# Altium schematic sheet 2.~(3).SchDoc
size 420 x 297 mm
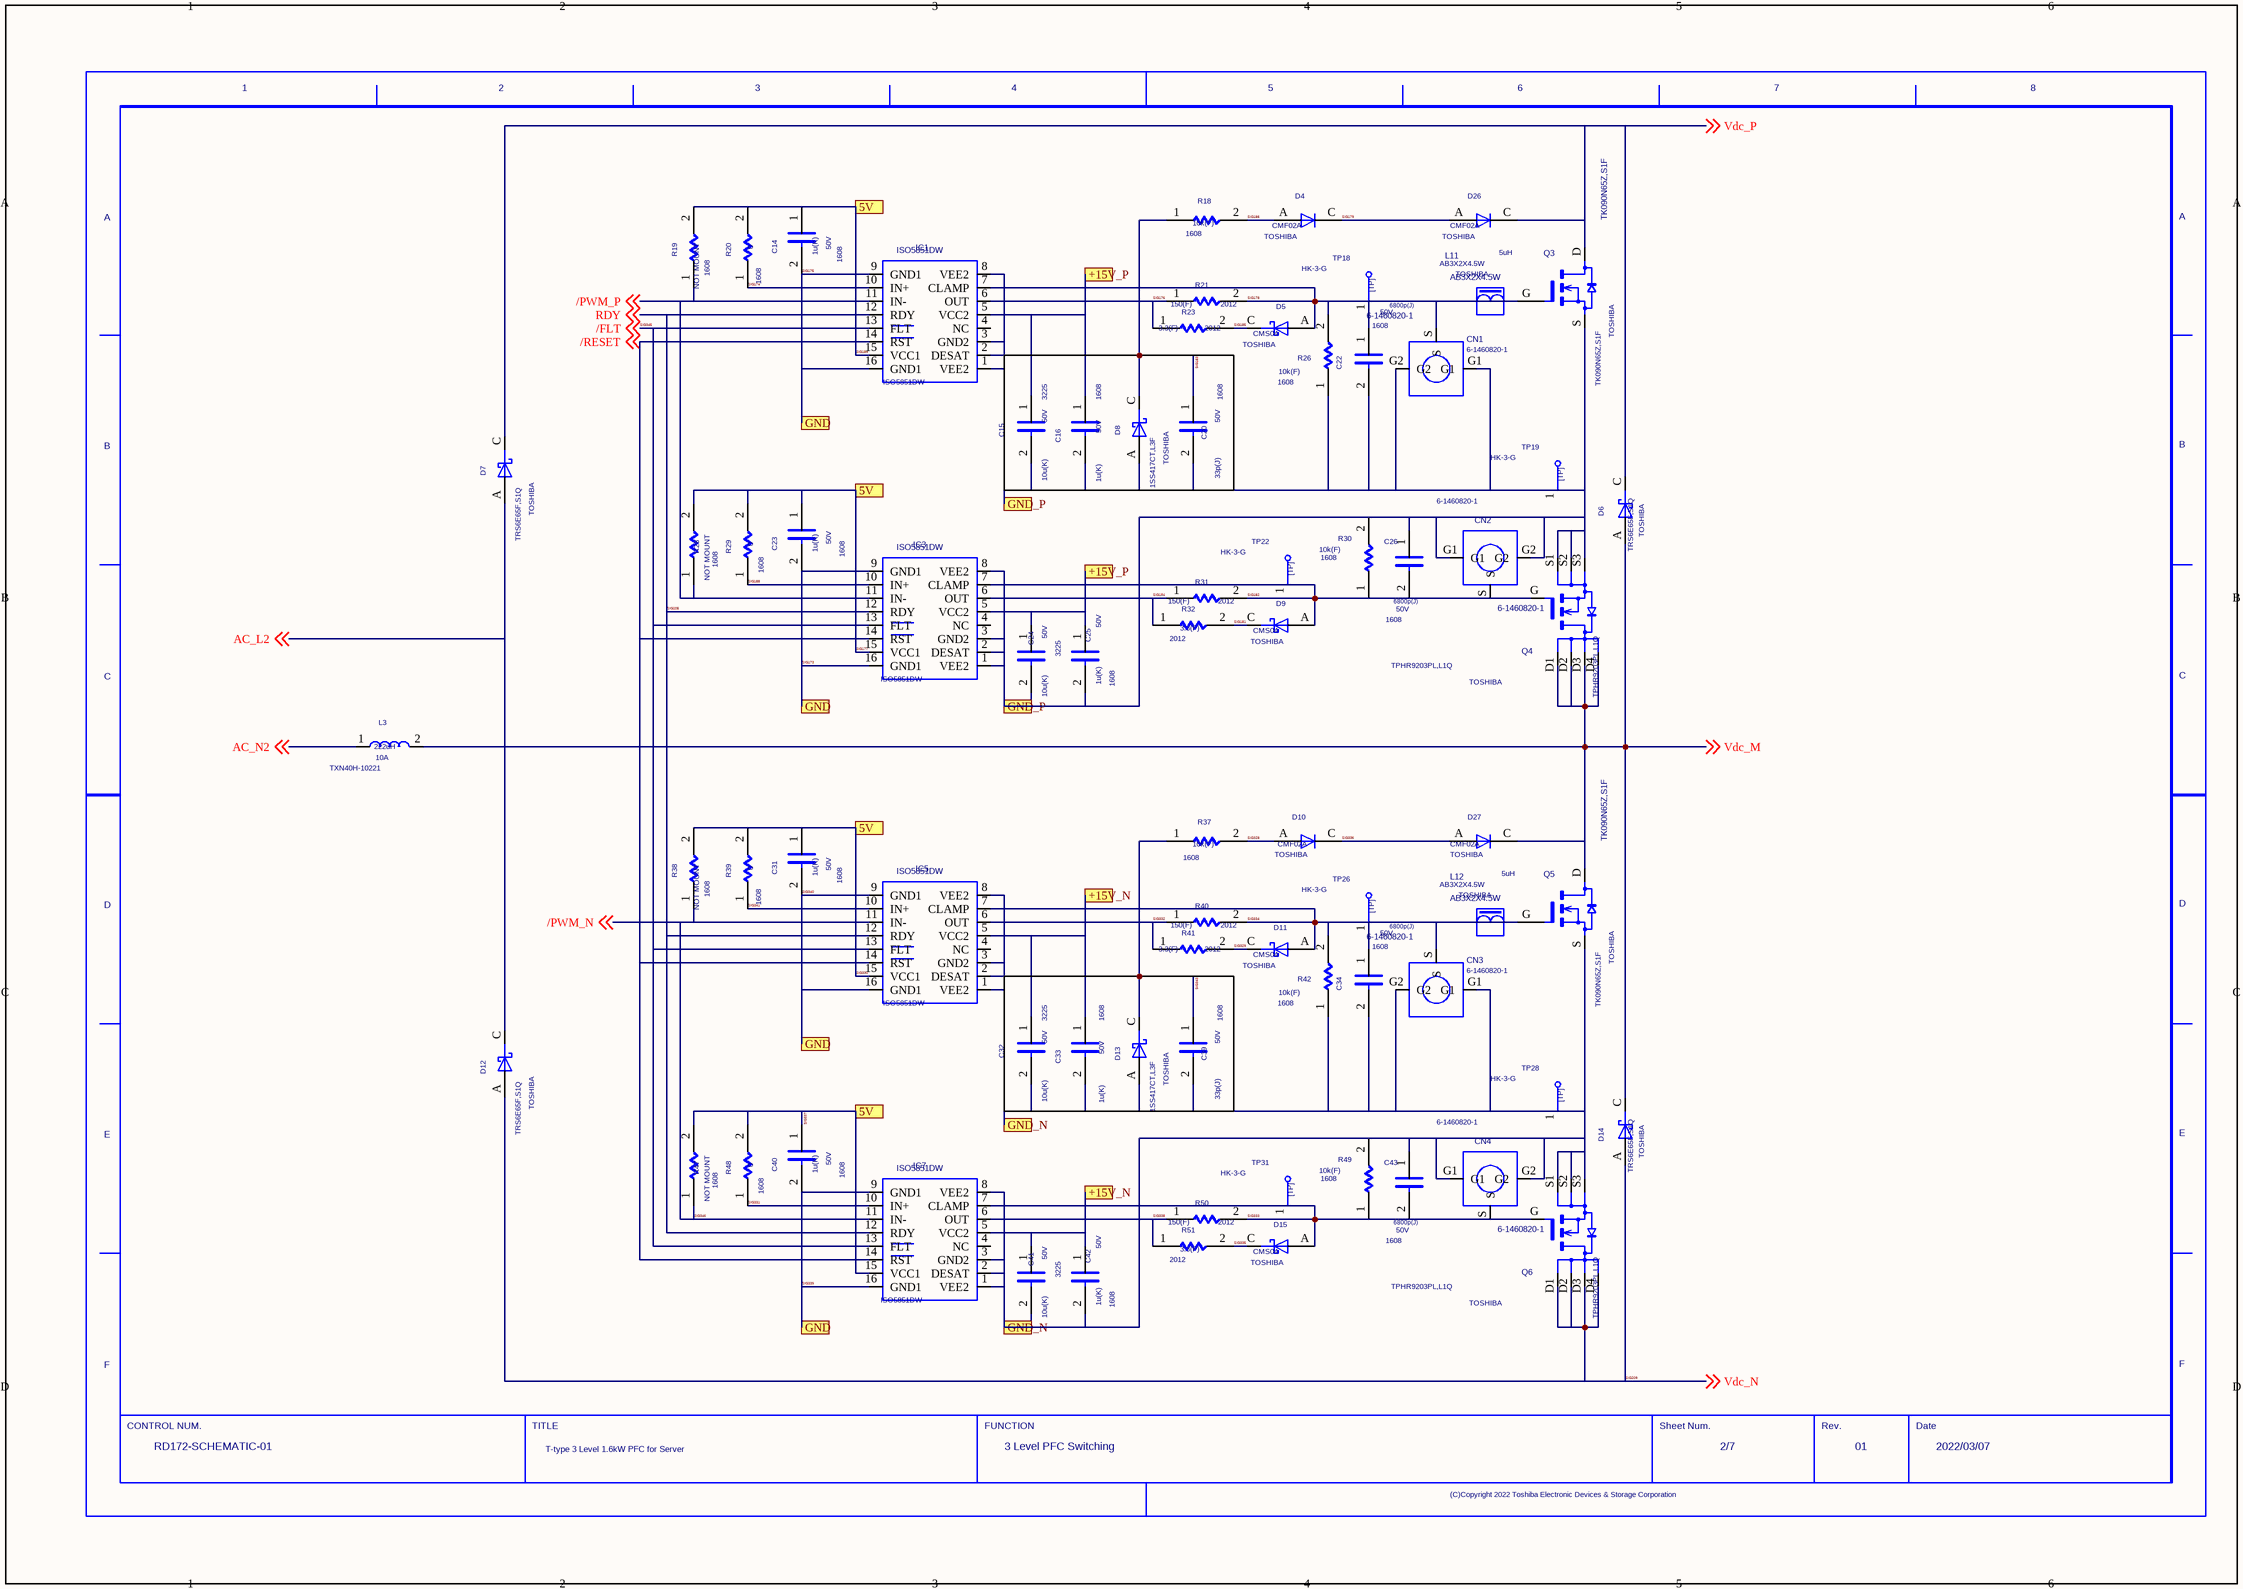
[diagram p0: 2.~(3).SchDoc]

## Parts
C14  SIZECODESMD: 1608  VAL2: 50V  VAL1: 1u(K)  (hidden comment: C)
C15  SIZECODESMD: 3225  VAL2: 50V  VAL1: 10u(K)  (hidden comment: C)
C16  SIZECODESMD: 1608  VAL2: 50V  VAL1: 1u(K)  (hidden comment: C)
C20  SIZECODESMD: 1608  VAL2: 50V  VAL1: 33p(J)  (hidden comment: C)
C22  SIZECODESMD: 1608  VAL2: 50V  VAL1: 6800p(J)  (hidden comment: C)
C23  SIZECODESMD: 1608  VAL2: 50V  VAL1: 1u(K)  (hidden comment: C)
C24  SIZECODESMD: 3225  VAL2: 50V  VAL1: 10u(K)  (hidden comment: C)
C25  SIZECODESMD: 1608  VAL2: 50V  VAL1: 1u(K)  (hidden comment: C)
C26  SIZECODESMD: 1608  VAL2: 50V  VAL1: 6800p(J)  (hidden comment: C)
C31  SIZECODESMD: 1608  VAL2: 50V  VAL1: 1u(K)  (hidden comment: C)
C32  SIZECODESMD: 3225  VAL2: 50V  VAL1: 10u(K)  (hidden comment: C)
C33  SIZECODESMD: 1608  VAL2: 50V  VAL1: 1u(K)  (hidden comment: C)
C34  SIZECODESMD: 1608  VAL2: 50V  VAL1: 6800p(J)  (hidden comment: C)
C39  SIZECODESMD: 1608  VAL2: 50V  VAL1: 33p(J)  (hidden comment: C)
C40  SIZECODESMD: 1608  VAL2: 50V  VAL1: 1u(K)  (hidden comment: C)
C41  SIZECODESMD: 3225  VAL2: 50V  VAL1: 10u(K)  (hidden comment: C)
C42  SIZECODESMD: 1608  VAL2: 50V  VAL1: 1u(K)  (hidden comment: C)
C43  SIZECODESMD: 1608  VAL2: 50V  VAL1: 6800p(J)  (hidden comment: C)
CN1  6-1460820-1
CN2  6-1460820-1
CN3  6-1460820-1
CN4  6-1460820-1
D4  VAL3: CMF02A  USERCOMPTEXT3: TOSHIBA  (hidden comment: D)
D5  USERCOMPTEXT3: TOSHIBA  VAL3: CMS04  (hidden comment: SBD)
D6  VAL3: TRS6E65F,S1Q  USERCOMPTEXT3: TOSHIBA  (hidden comment: SBD)
D7  USERCOMPTEXT3: TOSHIBA  VAL3: TRS6E65F,S1Q  (hidden comment: SBD)
D8  USERCOMPTEXT3: TOSHIBA  VAL3: 1SS417CT,L3F  (hidden comment: SBD)
D9  USERCOMPTEXT3: TOSHIBA  VAL3: CMS04  (hidden comment: SBD)
D10  VAL3: CMF02A  USERCOMPTEXT3: TOSHIBA  (hidden comment: D)
D11  USERCOMPTEXT3: TOSHIBA  VAL3: CMS04  (hidden comment: SBD)
D12  USERCOMPTEXT3: TOSHIBA  VAL3: TRS6E65F,S1Q  (hidden comment: SBD)
D13  USERCOMPTEXT3: TOSHIBA  VAL3: 1SS417CT,L3F  (hidden comment: SBD)
D14  VAL3: TRS6E65F,S1Q  USERCOMPTEXT3: TOSHIBA  (hidden comment: SBD)
D15  USERCOMPTEXT3: TOSHIBA  VAL3: CMS04  (hidden comment: SBD)
D26  VAL3: CMF02A  USERCOMPTEXT3: TOSHIBA  (hidden comment: D)
D27  VAL3: CMF02A  USERCOMPTEXT3: TOSHIBA  (hidden comment: D)
IC1  ISO5851DW
IC3  ISO5851DW
IC5  ISO5851DW
IC7  ISO5851DW
L3  VAL3: TXN40H-10221  VAL2: 10A  VAL1: 222uH  (hidden comment: L)
L11  AB3X2X4.5W  USERCOMPTEXT3: TOSHIBA  VAL1: 5uH
L12  AB3X2X4.5W  USERCOMPTEXT3: TOSHIBA  VAL1: 5uH
Q3  TK090N65Z,S1F  USERCOMPTEXT3: TOSHIBA
Q4  TPHR9203PL,L1Q  USERCOMPTEXT3: TOSHIBA
Q5  TK090N65Z,S1F  USERCOMPTEXT3: TOSHIBA
Q6  TPHR9203PL,L1Q  USERCOMPTEXT3: TOSHIBA
R18  SIZECODESMD: 1608  VAL1: 10k(F)  (hidden comment: R)
R19  SIZECODESMD: 1608  NOTMOUNT: NOT MOUNT  (hidden comment: R)
R20  SIZECODESMD: 1608  VAL1: 0  (hidden comment: R)
R21  SIZECODESMD: 2012  VAL1: 150(F)  (hidden comment: R)
R23  SIZECODESMD: 2012  VAL1: 3.3(F)  (hidden comment: R)
R26  SIZECODESMD: 1608  VAL1: 10k(F)  (hidden comment: R)
R28  SIZECODESMD: 1608  NOTMOUNT: NOT MOUNT  (hidden comment: R)
R29  SIZECODESMD: 1608  VAL1: 0  (hidden comment: R)
R30  SIZECODESMD: 1608  VAL1: 10k(F)  (hidden comment: R)
R31  SIZECODESMD: 2012  VAL1: 150(F)  (hidden comment: R)
R32  SIZECODESMD: 2012  VAL1: 3.3(F)  (hidden comment: R)
R37  SIZECODESMD: 1608  VAL1: 10k(F)  (hidden comment: R)
R38  SIZECODESMD: 1608  NOTMOUNT: NOT MOUNT  (hidden comment: R)
R39  SIZECODESMD: 1608  VAL1: 0  (hidden comment: R)
R40  SIZECODESMD: 2012  VAL1: 150(F)  (hidden comment: R)
R41  SIZECODESMD: 2012  VAL1: 3.3(F)  (hidden comment: R)
R42  SIZECODESMD: 1608  VAL1: 10k(F)  (hidden comment: R)
R47  SIZECODESMD: 1608  NOTMOUNT: NOT MOUNT  (hidden comment: R)
R48  SIZECODESMD: 1608  VAL1: 0  (hidden comment: R)
R49  SIZECODESMD: 1608  VAL1: 10k(F)  (hidden comment: R)
R50  SIZECODESMD: 2012  VAL1: 150(F)  (hidden comment: R)
R51  SIZECODESMD: 2012  VAL1: 3.3(F)  (hidden comment: R)
TP18  VAL3: HK-3-G  (hidden comment: TP)
TP19  VAL3: HK-3-G  (hidden comment: TP)
TP22  VAL3: HK-3-G  (hidden comment: TP)
TP26  VAL3: HK-3-G  (hidden comment: TP)
TP28  VAL3: HK-3-G  (hidden comment: TP)
TP31  VAL3: HK-3-G  (hidden comment: TP)
U?  DATE: 2022/03/07  REVISION: 01  SHEETNUMBER: 2/7  FUNCTION: 3 Level PFC Switching  TITLE: T-type 3 Level 1.6kW PFC for Server  DRAWINGNUMBER: RD172-SCHEMATIC-01  (hidden comment: WAKU_DEF100)

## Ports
5V, +15V_N, +15V_P, GND, GND_N, GND_P

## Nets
+15V_N: C32.1 C33.1 C41.1 C42.1 IC5.5(VCC2) IC7.5(VCC2) ; port +15V_N
+15V_P: C15.1 C16.1 C24.1 C25.1 IC1.5(VCC2) IC3.5(VCC2) ; port +15V_P
/PWM_P: IC1.11(IN-) IC3.11(IN-) R19.1 R28.1 ; off-sheet /PWM_P
/RESET: IC1.14(RST) IC3.14(RST) IC5.14(RST) IC7.14(RST) ; off-sheet /RESET
AC_L2: D7.A D12.C ; off-sheet AC_L2
AC_N2: L3.1 ; off-sheet AC_N2
GND_N: C32.2 C33.2 C34.2 C39.2 C41.2 C42.2 C43.1 CN3.G1 CN3.G2 CN4.G1 CN4.G2 D13.A IC5.1(VEE2) IC5.3(GND2) IC5.8(VEE2) IC7.1(VEE2) IC7.2(DESAT) IC7.3(GND2) IC7.8(VEE2) Q5.S Q6.S1 Q6.S2 Q6.S3 R42.1 R49.2 TP28.1 ; port GND_N
GND_P: C15.2 C16.2 C20.2 C22.2 C24.2 C25.2 C26.1 CN1.G1 CN1.G2 CN2.G1 CN2.G2 D8.A IC1.1(VEE2) IC1.3(GND2) IC1.8(VEE2) IC3.1(VEE2) IC3.2(DESAT) IC3.3(GND2) IC3.8(VEE2) Q3.S Q4.S1 Q4.S2 Q4.S3 R26.1 R30.2 TP19.1 ; port GND_P
SIG173: C14.2 C23.2 C31.2 C40.2 IC1.9(GND1) IC1.16(GND1) IC3.9(GND1) IC3.16(GND1) IC5.9(GND1) IC5.16(GND1) IC7.9(GND1) IC7.16(GND1) ; port GND  [also labelled SIG175, SIG339, SIG340]
SIG174: IC1.10(IN+) R20.1
SIG176: IC1.6(OUT) R21.1 R23.1
SIG177: C14.1 C23.1 C31.1 C40.1 IC1.15(VCC1) IC3.15(VCC1) IC5.15(VCC1) IC7.15(VCC1) R19.2 R20.2 R28.2 R29.2 R38.2 R39.2 R47.2 R48.2 ; port 5V  [also labelled SIG189, SIG330, SIG337]
SIG178: C22.1 CN1.S D5.A IC1.7(CLAMP) Q3.G R21.2 R26.2 TP18.1
SIG179: D4.C D26.A
SIG181: D9.C R32.2
SIG182: C26.2 CN2.S D9.A IC3.7(CLAMP) Q4.G R30.1 R31.2 TP22.1
SIG183: C20.1 D8.C IC1.2(DESAT) R18.1
SIG184: IC3.6(OUT) R31.1 R32.1
SIG185: D5.C R23.2
SIG186: D4.A R18.2
SIG188: IC3.10(IN+) R29.1
SIG205: IC1.12(RDY) IC3.12(RDY) IC5.12(RDY) IC7.12(RDY) ; off-sheet RDY  [also labelled RDY]
SIG209: D12.A D14.A Q6.D1 Q6.D2 Q6.D3 Q6.D4 ; off-sheet Vdc_N  [also labelled Vdc_N]
SIG328: D10.A R37.2
SIG329: D11.C R41.2
SIG331: IC7.10(IN+) R48.1
SIG332: IC5.6(OUT) R40.1 R41.1
SIG333: C43.2 CN4.S D15.A IC7.7(CLAMP) Q6.G R49.1 R50.2 TP31.1
SIG334: C34.1 CN3.S D11.A IC5.7(CLAMP) Q5.G R40.2 R42.2 TP26.1
SIG335: D15.C R51.2
SIG336: D10.C D27.A
SIG338: IC7.6(OUT) R50.1 R51.1
SIG341: IC5.10(IN+) R39.1
SIG343: C39.1 D13.C IC5.2(DESAT) R37.1
SIG345: IC1.13(FLT) IC3.13(FLT) IC5.13(FLT) IC7.13(FLT) ; off-sheet /FLT  [also labelled /FLT]
SIG346: IC5.11(IN-) IC7.11(IN-) R38.1 R47.1 ; off-sheet /PWM_N  [also labelled /PWM_N]
Vdc_M: D6.A D14.C D27.C L3.2 Q4.D1 Q4.D2 Q4.D3 Q4.D4 Q5.D ; off-sheet Vdc_M
Vdc_P: D6.C D7.C D26.C Q3.D ; off-sheet Vdc_P

Not connected (* = marked no-connect by the designer): IC1 4(NC); IC3 4(NC); IC5 4(NC); IC7 4(NC)

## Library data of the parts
C14 C16 C23 C25 C31 C33 C40 C42 = C: OriginalSymbolOrigin: (2540,7620); COMP: -C-UMK107AB7105KA-T
C15 C24 C32 C41 = C: OriginalSymbolOrigin: (2540,7620); COMP: -C-UMK325AB7106KM-T
C20 C39 = C: OriginalSymbolOrigin: (2540,7620); COMP: -C-CGA3E2C0G1H330J080AA
C22 C26 C34 C43 = C: OriginalSymbolOrigin: (2540,7620); COMP: -C-GRM1885C1H682JA01D
CN1-CN4 = 6_1460820_1: MMCX Connector, 170V; MANUFACTURER: TE Connectivity; COMP: -CN-6-1460820-1; TIME: 16:53:54; UPDATEUSER: t5459927; UPDATETIME: 16:17:04; SAVECOUNT: 3; SAVEAREA0: -4427,-12981,14210,683; OriginalSymbolOrigin: (0,0)
D4 D10 D26 D27 = D: SAVEAREA0: -225,-91,12804,7836; SAVECOUNT: 3; TIME: 14:49:55; UPDATEUSER: 19870035; UPDATETIME: 14:20:16; OriginalSymbolOrigin: (5080,5080); COMP: -D-CMF05_AC
D5 D9 D11 D15 = SBD: SAVEAREA0: -4630,-153,17114,13055; TIME: 14:49:55; UPDATEUSER: fukuda-y; UPDATETIME: 08:16:22; SAVECOUNT: 9; OriginalSymbolOrigin: (5080,5080); COMP: -D-CMS04_TE12L_Q_AC; VAL1: CMS04(TE12L,Q,M)
D6 D7 D12 D14 = SBD: SAVEAREA0: -4630,-153,17114,13055; TIME: 14:49:55; UPDATEUSER: fukuda-y; UPDATETIME: 08:16:22; SAVECOUNT: 9; OriginalSymbolOrigin: (5080,5080); COMP: -D-TRS6E65F_S1Q_AC
D8 D13 = SBD: SAVEAREA0: -4630,-153,17114,13055; TIME: 14:49:55; UPDATEUSER: fukuda-y; UPDATETIME: 08:16:22; SAVECOUNT: 9; OriginalSymbolOrigin: (5080,5080); COMP: -D-1SS417CTL3F_AC
IC1 IC3 IC5 IC7 = ISO5851DW: Gate Driver; MANUFACTURER: Txsas Instruments; COMP: -IC-ISO5851DWR; TIME: 16:53:55; UPDATEUSER: t5459927; UPDATETIME: 16:13:36; SAVECOUNT: 2; SAVEAREA0: -16530,-29444,33798,7453; OriginalSymbolOrigin: (0,0)
L3 = L: OriginalSymbolOrigin: (2540,5080); COMP: -L-TXN40H-10221
L11 L12 = AB3X2X4_5W: AMOBEADS; TIME: 16:53:53; UPDATEUSER: t5459927; SAVECOUNT: 1; SAVEAREA0: -1267,-5201,6185,262; OriginalSymbolOrigin: (0,0); INSTANCENAME: INS19006446
Q3 Q5 = TK090N65Z,S1F: Power MOS FET; COMP: -Q-TK090N65Z; NOTE: 650V 30A; TIME: 16:53:56; UPDATEUSER: t5459927; SAVECOUNT: 1; OriginalSymbolOrigin: (0,0); INSTANCENAME: INS18162118
Q4 Q6 = TPHR9203PL,L1Q: Power MOS FET; COMP: -Q-TPHR9203PL_GDS; NOTE: 30V, 150A; TIME: 16:53:55; UPDATEUSER: t5459927; SAVECOUNT: 1; OriginalSymbolOrigin: (0,0); INSTANCENAME: INS18653275
R18 R37 = R: OriginalSymbolOrigin: (5080,5080); COMP: -R-ERJ3EKF1002V; VAL2: 100mW
R19 R28 R38 R47 = R: OriginalSymbolOrigin: (5080,5080); COMP: -R-NC_R1608
R20 R29 R39 R48 = R: OriginalSymbolOrigin: (5080,5080); VAL2: 1A; COMP: -R-RK73Z1JTTD
R21 R31 R40 R50 = R: OriginalSymbolOrigin: (5080,5080); COMP: -R-RK73H2ATTD1500F; VAL2: 250mW
R23 R32 R41 R51 = R: OriginalSymbolOrigin: (5080,5080); COMP: -R-ERJ6DQF3R3V; VAL2: 500mW
R26 R30 R42 R49 = R: OriginalSymbolOrigin: (5080,5080); VAL2: 100mW; COMP: -R-ERJ3EKF1002V
TP18 TP19 TP22 TP26 TP28 TP31 = TP: TIME: 16:12:21; UPDATEUSER: fukuda-y; UPDATETIME: 16:18:11; SAVECOUNT: 2; SAVEAREA0: -242,-92,12810,7836; OriginalSymbolOrigin: (0,7620); COMP: -TP-HK-3-G
U? = WAKU_DEF100: PLOTTIME: HH:MM; SAVEAREA0: 148187,-66180,486823,89919; TIME: 14:30:25; UPDATEUSER: t5459927; UPDATETIME: 09:34:24; SAVECOUNT: 6; OriginalSymbolOrigin: (10160,284480)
